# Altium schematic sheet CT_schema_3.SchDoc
size 204 x 169 mm
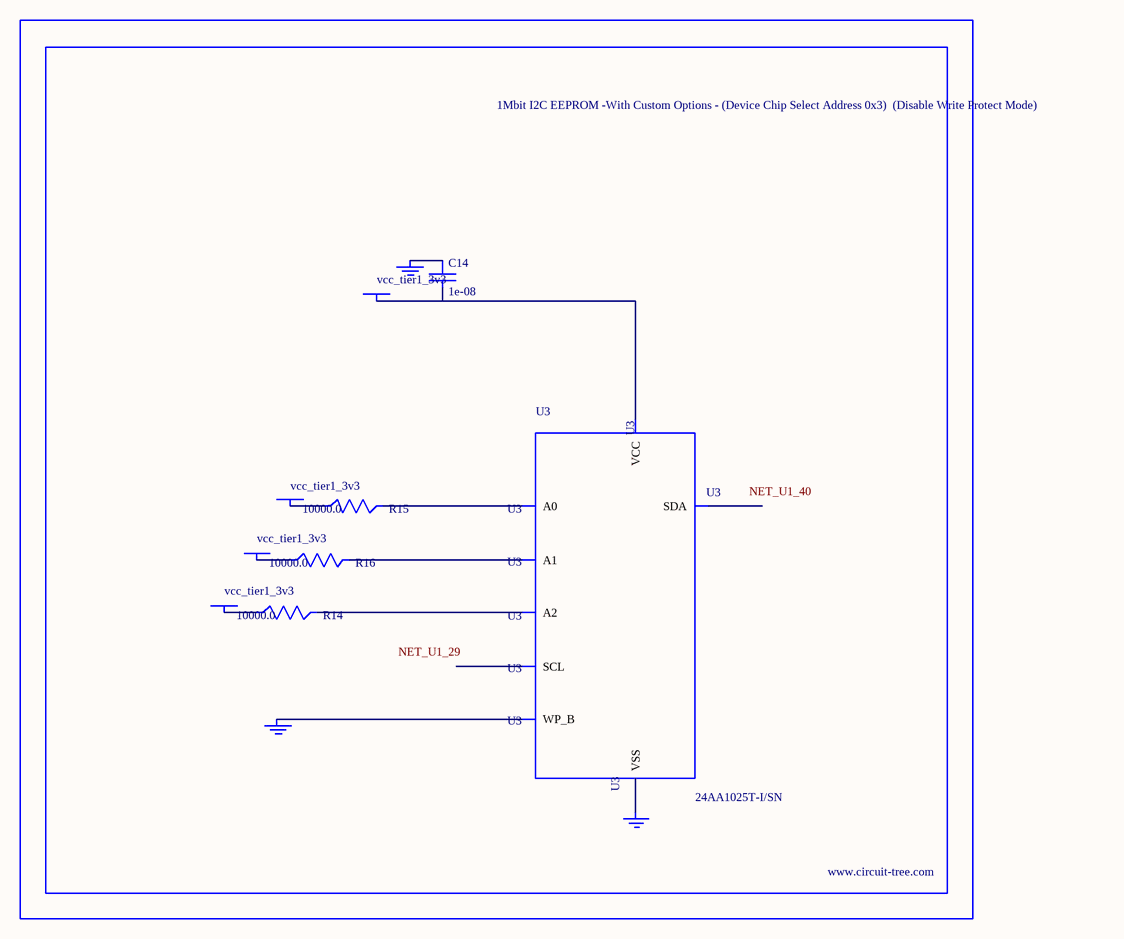
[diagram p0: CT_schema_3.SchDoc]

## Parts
BORDER2  (no value)
C14  1e-08  [C0402]
GND_INSTANCE_2_0  (no value)
GND_INSTANCE_2_1  (no value)
GND_INSTANCE_2_2  (no value)
POWER_INSTANCE_2_0  vcc_tier1_3v3
POWER_INSTANCE_2_1  vcc_tier1_3v3
POWER_INSTANCE_2_2  vcc_tier1_3v3
POWER_INSTANCE_2_3  vcc_tier1_3v3
R14  10000.0  [R0603]
R15  10000.0  [R0603]
R16  10000.0  [R0603]
U3  24AA1025T-I/SN  [SOIC-8]

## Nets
NetC14_1: C14.1 GND_INSTANCE_2_1.0(GND)
NetC14_2: C14.2 POWER_INSTANCE_2_3.0(PWR) U3.8(VCC)
NetGND_INSTANCE_2_0_0: GND_INSTANCE_2_0.0(GND) U3.7(WP_B)
NetGND_INSTANCE_2_2_0: GND_INSTANCE_2_2.0(GND) U3.4(VSS)
NetPOWER_INSTANCE_2_0_0: POWER_INSTANCE_2_0.0(PWR) R15.1
NetPOWER_INSTANCE_2_1_0: POWER_INSTANCE_2_1.0(PWR) R16.1
NetPOWER_INSTANCE_2_2_0: POWER_INSTANCE_2_2.0(PWR) R14.1
NetR14_2: R14.2 U3.3(A2)
NetR15_2: R15.2 U3.1(A0)
NetR16_2: R16.2 U3.2(A1)

Not connected (* = marked no-connect by the designer): U3 5(SDA) 6(SCL)

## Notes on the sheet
- Labels drawn without touching a wire or pin: NET_U1_29, NET_U1_40

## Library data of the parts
BORDER2 = BORDER_PAGE2
C14 = C0402C103K3RAC
GND_INSTANCE_2_0-GND_INSTANCE_2_2 = GND
POWER_INSTANCE_2_0-POWER_INSTANCE_2_3 = PWR
R14-R16 = RC0603JR-0710KL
